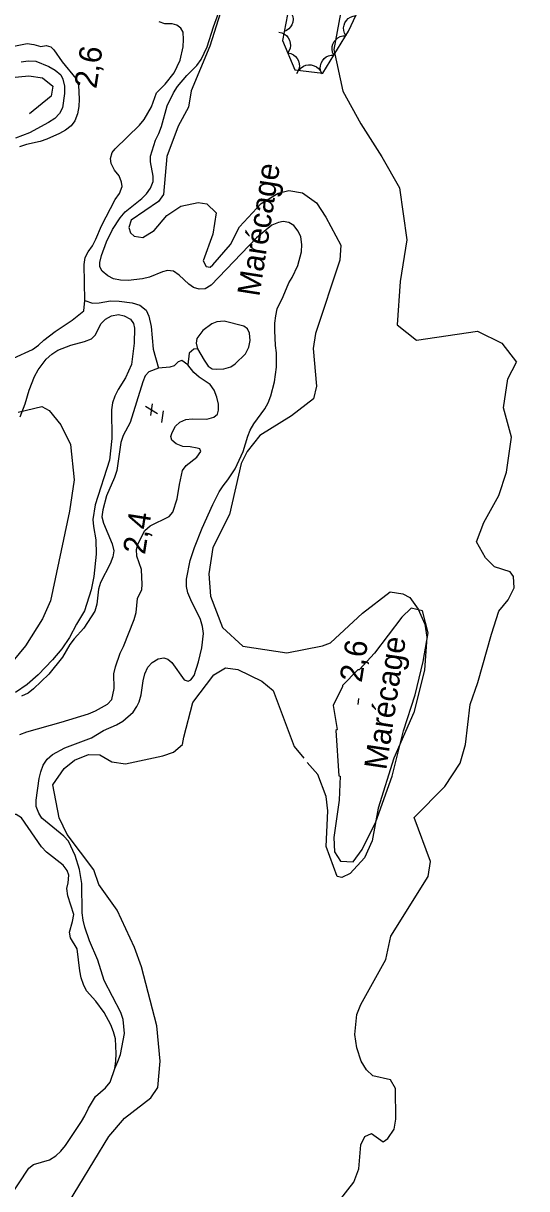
# Model space of a CAD drawing. Extents: x 282461 to 284471, y 5554090 to 5557646.
# Drawn here: x 283452.6 to 283519.7, y 5555386.5 to 5555541.8 of the extents above; entities that cross this region are included whole.
import ezdxf

# ---------------------------------------------------------------- set-up
doc = ezdxf.new("R2010")
doc.units = 0
for name, color, linetype in [('Niveau 2', 7, 'Continuous'), ('Niveau 3', 7, 'Continuous'), ('Niveau 4', 7, 'Continuous'), ('Niveau 44', 7, 'Continuous'), ('Niveau 7', 7, 'Continuous')]:
    doc.layers.add(name, color=color, linetype=linetype)

msp = doc.modelspace()

# ---------------------------------------------------------------- linework, layer by layer
at = {"layer": 'Niveau 2'}
for points in [[(283519.73, 5555546.77), (283512.04, 5555549.95), (283507.85, 5555551.08), (283503.91, 5555551.29), (283500.66, 5555550.57), (283497.2, 5555548.01), (283495.15, 5555544.29), (283494.04, 5555538.28), (283495.24, 5555532.74), (283497.6, 5555528.36), (283500.42, 5555523.99), (283502.78, 5555519.85), (283503.76, 5555512.92), (283502.88, 5555507.37), (283502.47, 5555501.59), (283505.04, 5555499.53), (283513.15, 5555500.74), (283516.41, 5555499.14), (283518.39, 5555496.61)], [(283479.78, 5555545.91), (283477.48, 5555538.73), (283475, 5555532.77), (283474.67, 5555530.59), (283473.26, 5555528.09), (283471.77, 5555524.03), (283471.33, 5555518.98), (283470.65, 5555518.03), (283467.03, 5555515.55), (283466.71, 5555514.57), (283466.94, 5555513.85), (283467.39, 5555513.43), (283468.57, 5555513.25), (283470.06, 5555514.18), (283471.75, 5555516.16), (283473.63, 5555517.41), (283475.96, 5555517.91), (283477.11, 5555517.72), (283478.33, 5555516.52), (283477.89, 5555513.68), (283476.62, 5555510.11), (283477.02, 5555509.37), (283477.53, 5555509.28), (283477.9, 5555509.58), (283480.23, 5555512.28), (283481.46, 5555514.67), (283484.34, 5555517.78), (283486.61, 5555519.16), (283488.01, 5555519.48), (283489.84, 5555519.2), (283491.71, 5555517.87), (283492.96, 5555515.96), (283494.96, 5555512.22), (283494.81, 5555510.2), (283491.59, 5555500.44), (283491.28, 5555498.42), (283491.71, 5555493.41), (283491.31, 5555491.75), (283488.36, 5555489.48), (283484.17, 5555486.84), (283482.46, 5555484.71), (283481.69, 5555483.13), (283480.13, 5555476.34), (283477.9, 5555471.91), (283477.37, 5555468.41), (283477.59, 5555465.45), (283479.17, 5555461.26), (283481.9, 5555458.79), (283487.75, 5555457.89), (283492.52, 5555458.84), (283493.59, 5555459.21), (283497.83, 5555463.18), (283501.53, 5555466), (283503.2, 5555465.76), (283504.14, 5555465.25), (283505.28, 5555463.71), (283506.15, 5555461.71), (283506.4, 5555459.96), (283506.09, 5555455.56), (283504.67, 5555449.95), (283502.03, 5555443.87), (283499.95, 5555437.18), (283499.12, 5555432.85)], [(283447.81, 5555527.57), (283446.63, 5555527.76), (283445.39, 5555528.47), (283444.09, 5555530.21), (283444, 5555530.74), (283444.51, 5555531.85), (283446.11, 5555533.33), (283447.81, 5555534.24), (283453.38, 5555534.77), (283455.21, 5555534.49), (283456.56, 5555533.39), (283456.36, 5555532.07), (283453.46, 5555529.7)], [(283504.71, 5555435.94), (283508.8, 5555440.07), (283510.84, 5555443.2), (283511.58, 5555445.66), (283512.21, 5555451.02), (283513.2, 5555453.95), (283515.02, 5555460.36), (283516.02, 5555463.42), (283517.28, 5555464.94), (283518.06, 5555466.53), (283517.95, 5555468.08), (283517.53, 5555468.67), (283515.42, 5555469.36), (283514.23, 5555470.55), (283513.02, 5555472.7), (283514.01, 5555475.24), (283516.01, 5555478.84), (283517.02, 5555481.94), (283517.71, 5555486.61), (283516.65, 5555490.55), (283517.23, 5555494.39), (283518.39, 5555496.61)], [(283451.94, 5555489.94), (283455.09, 5555490.69), (283456.07, 5555490.19), (283457.64, 5555488.25), (283458.94, 5555485.63), (283459.43, 5555480.93), (283458.77, 5555476.76), (283456.26, 5555464.82), (283455.18, 5555462.43), (283452.94, 5555458.83), (283450.17, 5555455.47)], [(283462.71, 5555427.02), (283462.03, 5555428.99), (283458.46, 5555433.67), (283457.43, 5555435.89), (283456.56, 5555440.31), (283458.09, 5555442.46), (283459.46, 5555443.6), (283461.31, 5555444.33), (283462.84, 5555444.28), (283464.42, 5555443.37), (283466.27, 5555443.09), (283471.21, 5555444.17), (283472.67, 5555444.64), (283473.86, 5555445.66), (283474.01, 5555446.67), (283475.24, 5555451.26), (283478.03, 5555454.95), (283479.57, 5555455.9), (283481.23, 5555455.67), (283484.42, 5555454.11), (283485.93, 5555452.85), (283488.73, 5555445.42), (283490.03, 5555443.85)], [(283499.12, 5555432.85), (283498.09, 5555430.59), (283496.21, 5555428.5), (283495.11, 5555427.97), (283494.45, 5555428.07), (283493.01, 5555432.08), (283493.23, 5555436.83), (283493.01, 5555438.75), (283491.9, 5555441.66), (283490.46, 5555443.28)], [(283492.87, 5555382.47), (283496.7, 5555387.35), (283497.34, 5555389.13), (283497.62, 5555392.32), (283498.15, 5555393.45), (283499.05, 5555393.84), (283500.62, 5555392.73), (283501.2, 5555393.15), (283502.08, 5555394.39), (283502.27, 5555395.74), (283502.25, 5555399.84), (283501.57, 5555400.98), (283499.24, 5555401.51), (283498.36, 5555402.34), (283497.65, 5555403.47), (283497.07, 5555405.26), (283496.83, 5555407.01), (283497.08, 5555409.7), (283497.63, 5555411.01), (283500.95, 5555417), (283501.61, 5555420.13), (283506.61, 5555428.09), (283506.92, 5555430.09), (283504.71, 5555435.94)], [(283450.25, 5555366.31), (283452.84, 5555369.65), (283454.28, 5555372.38), (283454.52, 5555374.88), (283454.55, 5555377.46), (283454.92, 5555378.76), (283456.37, 5555381.45), (283458.05, 5555383.59), (283464.03, 5555393.44), (283466.12, 5555395.87), (283469.65, 5555398.57), (283470.56, 5555399.95), (283470.89, 5555403.47), (283470.44, 5555408.18), (283468.4, 5555416.04), (283467.43, 5555418.6), (283465.12, 5555423.58), (283462.71, 5555427.02)]]:
    msp.add_lwpolyline(points, dxfattribs=at)
at = {"layer": 'Niveau 3'}
for p, q in [((283468.9, 5555490.77), (283470.53, 5555489.77)), ((283469.61, 5555489.51), (283469.86, 5555491.05)), ((283471.09, 5555488.57), (283471.33, 5555490.15)), ((283497.25, 5555451.01), (283497.37, 5555451.8))]:
    msp.add_line(p, q, dxfattribs=at)
at = {"layer": 'Niveau 4'}
for points in [[(283451.31, 5555497.15), (283453.86, 5555498.32), (283454.67, 5555498.9), (283455.36, 5555499.55), (283456.86, 5555500.71), (283459.16, 5555502.23), (283460.72, 5555503.45), (283460.83, 5555504.84), (283460.73, 5555509.64), (283460.89, 5555510.57), (283461.29, 5555511.32), (283461.87, 5555512.13), (283462.32, 5555513.01), (283463.06, 5555514.8), (283464.89, 5555518.28), (283465.46, 5555519.1), (283465.8, 5555520.03), (283465.74, 5555520.6), (283465.39, 5555521.47), (283464.8, 5555522.22), (283464.33, 5555523.08), (283464.26, 5555523.77), (283464.49, 5555524.58), (283464.89, 5555525.05), (283468.11, 5555528.19), (283468.75, 5555528.95), (283469.72, 5555530.63), (283470.4, 5555532.49), (283471.55, 5555533.65), (283472.76, 5555535.17), (283473.56, 5555536.85), (283473.95, 5555538.64), (283474, 5555539.63), (283473.93, 5555540.61), (283473.64, 5555541.13), (283473.11, 5555541.53), (283472.47, 5555541.7), (283471.48, 5555541.69), (283470.73, 5555541.98)], [(283451.36, 5555538.72), (283453.16, 5555539.08), (283454.03, 5555538.97), (283454.96, 5555538.69), (283455.66, 5555538.81), (283456.3, 5555538.64), (283456.71, 5555538.24), (283457.82, 5555536.63), (283459.64, 5555534.44), (283460, 5555533.52), (283460.07, 5555531.67), (283460.02, 5555530.68), (283459.86, 5555529.7), (283459.52, 5555528.77), (283459, 5555528.13), (283458.25, 5555527.55), (283457.44, 5555527.08), (283455.76, 5555526.32), (283454.9, 5555526.02), (283453.04, 5555525.61), (283452.12, 5555525.31)], [(283460.83, 5555504.84), (283461.87, 5555504.5), (283462.74, 5555504.51), (283464.25, 5555504.81), (283465.41, 5555504.76), (283467.16, 5555504.54), (283468.15, 5555504.2), (283469.02, 5555503.57), (283469.38, 5555502.76), (283469.68, 5555501.37), (283469.94, 5555498.37), (283470.67, 5555495.81)], [(283476.56, 5555500.83), (283475.76, 5555499.77), (283475.65, 5555499.13), (283475.83, 5555498.4), (283476.73, 5555496.87), (283477.26, 5555496.07), (283477.79, 5555495.72), (283478.37, 5555495.67), (283479.36, 5555495.74), (283480.29, 5555495.99), (283480.87, 5555496.4), (283482.25, 5555497.75), (283482.7, 5555498.63), (283482.87, 5555499.5), (283482.8, 5555500.49), (283482.5, 5555501.07), (283482.03, 5555501.41), (283479.4, 5555502.08), (283478.41, 5555502.01), (283477.78, 5555501.71), (283476.56, 5555500.83)], [(283475.83, 5555498.4), (283475.36, 5555498.33), (283474.73, 5555497.8), (283474.54, 5555496.26)], [(283467.84, 5555465.14), (283468.41, 5555466.31), (283468.46, 5555467.01), (283468.38, 5555468.99), (283467.77, 5555470.78), (283467.7, 5555471.65), (283467.93, 5555472.47), (283468.84, 5555474.17), (283469.53, 5555474.81), (283472.08, 5555476.06), (283472.54, 5555476.65), (283473.16, 5555478.4), (283473.43, 5555480.32), (283473.87, 5555482.19), (283474.33, 5555482.83), (283475.77, 5555483.96), (283476.29, 5555484.72), (283476.16, 5555485.06), (283475.81, 5555485.18), (283474.88, 5555485.34), (283473.89, 5555485.39), (283473.01, 5555485.73), (283472.42, 5555486.24), (283472.3, 5555486.71), (283472.47, 5555487.23), (283472.93, 5555488.11), (283473.5, 5555488.64), (283474.31, 5555489), (283475.13, 5555489.06), (283477.11, 5555489.03), (283478.04, 5555489.27), (283478.5, 5555489.68), (283478.67, 5555490.21), (283478.66, 5555491.02), (283478.41, 5555491.95), (283478.05, 5555492.88), (283477.52, 5555493.63), (283476.05, 5555494.6), (283475.35, 5555495.23), (283474.54, 5555496.26), (283473.76, 5555496.84), (283473.29, 5555496.66), (283472.72, 5555496.13), (283472.14, 5555495.95), (283470.67, 5555495.81), (283469.35, 5555495.33), (283468.89, 5555494.81), (283468.55, 5555493.99), (283466.87, 5555488.56), (283465.95, 5555486.86), (283465.62, 5555485.93), (283465.08, 5555482.2), (283464.8, 5555481.27), (283463.72, 5555478.82), (283463.22, 5555476.95), (283463.11, 5555476.02), (283463.3, 5555475.15), (283464.49, 5555472.43), (283464.68, 5555471.5), (283464.57, 5555470.69), (283464.23, 5555469.75), (283462.92, 5555467.24), (283462.64, 5555466.36), (283462.43, 5555464.38), (283462.15, 5555463.45), (283460.72, 5555461.16), (283459.4, 5555459.75), (283458.83, 5555458.99), (283457.86, 5555457.3), (283456.02, 5555455.06), (283454.01, 5555453.07), (283453.26, 5555452.53), (283452.39, 5555452.12)], [(283452.16, 5555447), (283453.08, 5555447.36), (283457.67, 5555448.63), (283461.32, 5555449.78), (283462.25, 5555450.14), (283463.87, 5555451.03), (283464.44, 5555451.67), (283464.72, 5555453.13), (283464.7, 5555455.11), (283464.92, 5555456.04), (283465.54, 5555457.85), (283465.99, 5555458.73), (283467.41, 5555462.35), (283467.69, 5555463.28), (283467.84, 5555465.14)], [(283458.45, 5555426.49), (283458.62, 5555427.25), (283458.72, 5555428.24), (283458.48, 5555428.88), (283457.95, 5555429.57), (283455.72, 5555431.34), (283455.07, 5555432.03), (283452.4, 5555435.9), (283451.7, 5555436.36), (283451.23, 5555436.35), (283450.3, 5555436.57), (283448.95, 5555437.54), (283446.55, 5555439.09), (283445.65, 5555439.33), (283444.03, 5555439.99), (283443.33, 5555440.68), (283442.33, 5555441.19)], [(283449.35, 5555383.2), (283453.36, 5555389.23), (283453.99, 5555389.71), (283456.14, 5555390.31), (283456.95, 5555390.84), (283457.64, 5555391.49), (283458.27, 5555392.25), (283460.39, 5555395.42), (283460.84, 5555396.18), (283461.3, 5555397.23), (283462.27, 5555398.75), (283463.59, 5555399.93), (283464.22, 5555400.69), (283464.84, 5555402.5), (283464.95, 5555403.49), (283465, 5555404.48), (283464.91, 5555406.45), (283464.67, 5555407.38), (283464.31, 5555408.31), (283463.42, 5555409.98), (283462.29, 5555411.48), (283461.06, 5555412.86), (283460.64, 5555413.67), (283460.34, 5555414.6), (283460.15, 5555415.52), (283459.83, 5555418.43), (283458.94, 5555419.93), (283458.81, 5555420.68), (283459.2, 5555422.08), (283459.36, 5555423.01), (283458.58, 5555425.51), (283458.45, 5555426.49)]]:
    msp.add_lwpolyline(points, dxfattribs=at)
at = {"layer": 'Niveau 44'}
for points in [[(283511.65, 5555551.67), (283515.82, 5555551.7), (283516.28, 5555552.39), (283514.87, 5555554.23), (283509.75, 5555556.74), (283505.55, 5555559.48), (283502.29, 5555560.85), (283495.81, 5555559.65), (283491.42, 5555558), (283487.93, 5555558.21), (283484.44, 5555559.57), (283482.6, 5555557.94), (283485.18, 5555555.19), (283488.68, 5555552.9), (283489.63, 5555549.21), (283488.05, 5555544.12), (283487.16, 5555539.49), (283488.82, 5555535.58), (283492.54, 5555535.14), (283495.97, 5555540.71), (283498.02, 5555545.11), (283501.01, 5555548.13), (283508.17, 5555550.95), (283511.65, 5555551.67)], [(283487.95, 5555543.62), (283488.25, 5555543.33), (283488.44, 5555542.97), (283488.56, 5555542.66), (283488.58, 5555542.31), (283488.55, 5555541.94), (283488.41, 5555541.58), (283488.26, 5555541.29), (283488.02, 5555541.03), (283487.72, 5555540.81), (283487.39, 5555540.67)], [(283495.67, 5555540.08), (283495.46, 5555540.44), (283495.36, 5555540.83), (283495.32, 5555541.16), (283495.39, 5555541.51), (283495.51, 5555541.85), (283495.73, 5555542.17), (283495.94, 5555542.42), (283496.24, 5555542.6), (283496.59, 5555542.74), (283496.94, 5555542.8)], [(283486.69, 5555540.6), (283487.1, 5555540.52), (283487.46, 5555540.32), (283487.73, 5555540.13), (283487.95, 5555539.85), (283488.12, 5555539.53), (283488.21, 5555539.15), (283488.25, 5555538.83), (283488.19, 5555538.48), (283488.06, 5555538.13), (283487.87, 5555537.83)], [(283494.03, 5555537.55), (283493.85, 5555537.94), (283493.8, 5555538.34), (283493.8, 5555538.67), (283493.9, 5555539.01), (283494.07, 5555539.34), (283494.32, 5555539.63), (283494.56, 5555539.85), (283494.88, 5555540), (283495.24, 5555540.1), (283495.6, 5555540.11)], [(283487.87, 5555537.83), (283488.28, 5555537.75), (283488.64, 5555537.56), (283488.91, 5555537.36), (283489.12, 5555537.08), (283489.3, 5555536.76), (283489.38, 5555536.38), (283489.43, 5555536.06), (283489.36, 5555535.71), (283489.24, 5555535.36), (283489.04, 5555535.06)], [(283492.45, 5555534.99), (283492.28, 5555535.37), (283492.22, 5555535.78), (283492.23, 5555536.11), (283492.33, 5555536.45), (283492.49, 5555536.78), (283492.75, 5555537.07), (283492.99, 5555537.29), (283493.31, 5555537.44), (283493.67, 5555537.54), (283494.03, 5555537.55)], [(283489.38, 5555535.51), (283489.66, 5555535.83), (283490, 5555536.05), (283490.3, 5555536.19), (283490.65, 5555536.24), (283491.02, 5555536.22), (283491.39, 5555536.12), (283491.69, 5555535.99), (283491.96, 5555535.76), (283492.2, 5555535.48), (283492.37, 5555535.16)]]:
    msp.add_lwpolyline(points, dxfattribs=at)
at = {"layer": 'Niveau 7'}
for points in [[(283471.87, 5555508.85), (283471.17, 5555508.67), (283469.43, 5555507.95), (283468.51, 5555507.71), (283466.59, 5555507.51), (283465.6, 5555507.56), (283464.66, 5555507.72), (283463.9, 5555508.12), (283463.14, 5555508.75), (283462.84, 5555509.33), (283462.83, 5555509.91), (283463.05, 5555510.84), (283463.73, 5555512.65), (283464.53, 5555514.29), (283465.56, 5555515.87), (283466.19, 5555516.64), (283468.44, 5555518.41), (283469.07, 5555519.05), (283469.59, 5555519.82), (283469.93, 5555520.69), (283469.92, 5555521.39), (283469.6, 5555523.3), (283469.6, 5555524.06), (283470.24, 5555526.22), (283470.7, 5555527.1), (283471.04, 5555528.04), (283471.82, 5555530.78), (283472.67, 5555532.53), (283473.19, 5555533.35), (283474.45, 5555534.82), (283475.77, 5555536.17), (283476.35, 5555536.94), (283477.14, 5555538.63), (283477.98, 5555541.32), (283478.66, 5555543.13)], [(283452.36, 5555536.65), (283453.29, 5555536.78), (283454.28, 5555536.73), (283456.04, 5555536), (283456.86, 5555535.54), (283457.62, 5555534.91), (283457.92, 5555534.33), (283458.11, 5555533.41), (283458.12, 5555532.42), (283457.85, 5555530.5), (283457.45, 5555529.74), (283456.82, 5555529.09), (283456.01, 5555528.56), (283453.46, 5555527.19), (283451.61, 5555526.47)], [(283464.84, 5555402.5), (283465.24, 5555403.43), (283465.58, 5555404.37), (283466.13, 5555407.16), (283465.93, 5555409.02), (283465.63, 5555409.95), (283463.43, 5555414.23), (283462.58, 5555416.95), (283461.44, 5555419.49), (283460.84, 5555421.35), (283460.6, 5555422.27), (283460.47, 5555423.26), (283460.42, 5555427.15), (283460.11, 5555429.01), (283459.56, 5555430.86), (283458.67, 5555432.77), (283458.02, 5555433.46), (283455.08, 5555435.87), (283454.72, 5555436.51), (283454.36, 5555437.43), (283454.36, 5555438.25), (283454.73, 5555441.16), (283454.95, 5555442.03), (283455.29, 5555442.91), (283455.8, 5555443.73), (283456.5, 5555444.32), (283458.17, 5555445.21), (283461.71, 5555446.58), (283463.33, 5555447.53), (283465.07, 5555448.31), (283465.88, 5555448.78), (283467.26, 5555449.96), (283467.77, 5555450.72), (283468.06, 5555451.37), (283468.34, 5555452.3), (283468.61, 5555454.16), (283468.83, 5555455.1), (283469.23, 5555455.97), (283469.8, 5555456.62), (283470.61, 5555457.09), (283471.37, 5555457.22), (283471.89, 5555457.05), (283472.42, 5555456.59), (283474.08, 5555454.28), (283474.6, 5555454.12), (283474.95, 5555454.29), (283475.41, 5555454.88), (283475.97, 5555456.69), (283476.42, 5555458.56), (283476.63, 5555460.48), (283476.5, 5555461.4), (283476.26, 5555462.33), (283474.94, 5555464.93), (283474.58, 5555465.86), (283474.4, 5555466.73), (283474.39, 5555467.72), (283474.88, 5555470.17), (283475.44, 5555471.92), (283476.46, 5555474.49), (283477.88, 5555477.64), (283478.74, 5555479.34), (283479.25, 5555480.16), (283479.88, 5555480.92), (283480.85, 5555482.39), (283481.93, 5555484.72), (283482.55, 5555486.77), (283482.89, 5555487.58), (283483.35, 5555488.4), (283484.84, 5555490.4), (283485.29, 5555491.22), (283485.63, 5555492.15), (283486.13, 5555494.02), (283486.4, 5555495.94), (283486.38, 5555497.86), (283486.25, 5555498.85), (283486.17, 5555500.82), (283486.16, 5555501.81), (283486.27, 5555502.8), (283486.49, 5555503.73), (283487.28, 5555505.37), (283488.02, 5555507.18), (283488.48, 5555507.89), (283489.22, 5555509.52), (283489.72, 5555511.33), (283489.76, 5555512.32), (283489.64, 5555513.31), (283489.28, 5555514.06), (283488.69, 5555514.81), (283488.04, 5555515.21), (283487.28, 5555515.37), (283486.64, 5555515.25), (283485.77, 5555514.89), (283483.7, 5555513.18), (283477.66, 5555506.89), (283476.85, 5555506.41), (283476.09, 5555506.34), (283475.33, 5555506.57), (283474.69, 5555507.03), (283473.39, 5555508.23), (283472.63, 5555508.75), (283471.87, 5555508.85)], [(283452.22, 5555489.33), (283452.9, 5555491.08), (283453.4, 5555492.89), (283454.13, 5555494.7), (283454.59, 5555495.58), (283455.68, 5555497.04), (283456.43, 5555497.69), (283457.24, 5555498.22), (283458.98, 5555498.88), (283460.77, 5555499.37), (283461.7, 5555499.73), (283462.22, 5555500.2), (283463.02, 5555501.78), (283463.59, 5555502.37), (283464.4, 5555502.78), (283465.33, 5555502.97), (283466.09, 5555502.8), (283466.91, 5555502.35), (283467.32, 5555501.77), (283467.45, 5555501.13), (283467.41, 5555499.16), (283467.04, 5555496.3), (283466.24, 5555494.55), (283465.27, 5555492.97), (283464.82, 5555492.09), (283464.54, 5555491.22), (283464.37, 5555490.28), (283464.42, 5555486.45), (283464.1, 5555483.54), (283462.19, 5555477.59), (283461.92, 5555475.66), (283461.99, 5555474.73), (283462.31, 5555472.94), (283462.33, 5555471.02), (283462.01, 5555468.05), (283461.68, 5555466.3), (283460.79, 5555463.5), (283459.7, 5555461.69), (283458.79, 5555459.93), (283457.76, 5555458.41), (283456.5, 5555456.94), (283454.6, 5555454.94), (283453.16, 5555453.65), (283451.6, 5555452.58)], [(283494.89, 5555430.11), (283496.6, 5555430.03), (283497.79, 5555431.66), (283499.64, 5555435.35), (283501.81, 5555441.43), (283503.33, 5555447.51), (283504.85, 5555452.29), (283505.94, 5555456.75), (283506.59, 5555460.55), (283505.83, 5555463.48), (283504.32, 5555463.83), (283503.09, 5555462.62), (283499.46, 5555457.86), (283497.39, 5555455.61), (283497.24, 5555455.63), (283495.19, 5555453.55), (283495.17, 5555453.39), (283493.92, 5555450.85), (283494.46, 5555447.68), (283494.27, 5555447.53), (283494.71, 5555441.48), (283494.88, 5555441.46), (283494.73, 5555438.24), (283494.03, 5555433.29), (283494.12, 5555431.37), (283494.89, 5555430.11)]]:
    msp.add_lwpolyline(points, dxfattribs=at)

# ---------------------------------------------------------------- texts
at = {"layer": 'Niveau 3'}
for s, rotation, p in [('    2,6', 81.0958, (283461.67, 5555528.58)), ('    2,4', 81.0958, (283468.15, 5555466.5)), ('2,6  ', 81.0957, (283497.73, 5555453.85))]:
    msp.add_text(s, height=3, rotation=rotation, dxfattribs=at).set_placement(p)
at = {"layer": 'Niveau 7'}
for rotation, p in [(81.0598, (283484.09, 5555505.27)), (81.5139, (283501.01, 5555442.19))]:
    msp.add_text('Marécage', height=3, rotation=rotation, dxfattribs=at).set_placement(p)

doc.saveas('drawing.dxf')
